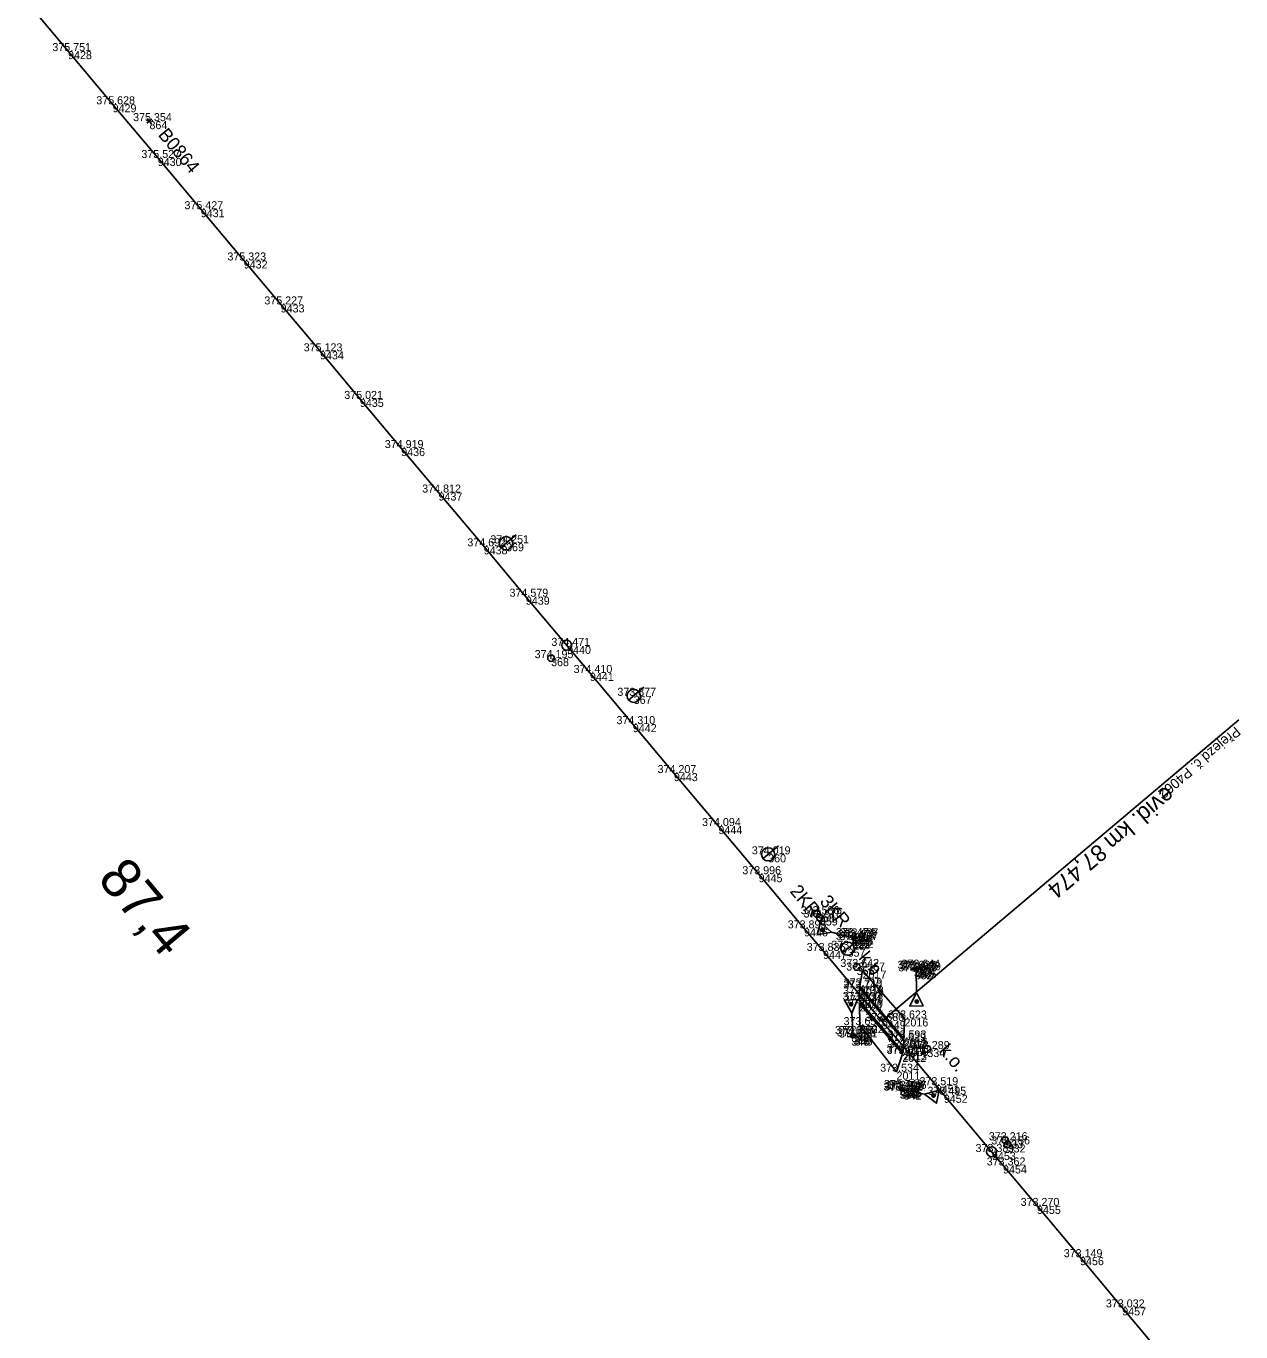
# Model space of a CAD drawing. Extents: x -599511 to -595511, y -1067427 to -1062061.
# Drawn here: x -596648.2 to -596466.1, y -1065669.8 to -1065474 of the extents above; entities that cross this region are included whole.
import ezdxf

# ---------------------------------------------------------------- set-up
doc = ezdxf.new("R2010")
doc.units = 0
for name, color, linetype in [('Vrstva 1', 7, 'Continuous'), ('Vrstva 12', 7, 'Continuous'), ('Vrstva 27', 7, 'Continuous'), ('Vrstva 4', 7, 'Continuous'), ('Vrstva 43', 7, 'Continuous'), ('Vrstva 50', 7, 'Continuous'), ('Vrstva 60', 7, 'Continuous'), ('Vrstva 61', 7, 'Continuous'), ('Vrstva 7', 7, 'Continuous')]:
    doc.layers.add(name, color=color, linetype=linetype)

msp = doc.modelspace()

# ---------------------------------------------------------------- linework, layer by layer
at = {"layer": 'Vrstva 1'}
msp.add_lwpolyline([(-596648.21, -1065470.29), (-596641.92, -1065477.78), (-596635.24, -1065485.75), (-596628.47, -1065493.8), (-596622.02, -1065501.48), (-596615.58, -1065509.16), (-596610.04, -1065515.75), (-596604.14, -1065522.78), (-596598.16, -1065529.91), (-596591.97, -1065537.28), (-596586.37, -1065543.95), (-596579.6, -1065552.01), (-596573.28, -1065559.56), (-596567.09, -1065566.93), (-596563.67, -1065570.99), (-596557.24, -1065578.66), (-596551.08, -1065586), (-596544.41, -1065593.94), (-596538.37, -1065601.16), (-596531.57, -1065609.27), (-596528.72, -1065612.66), (-596523.26, -1065619.18), (-596519.9, -1065623.17), (-596516.48, -1065627.21), (-596511.81, -1065632.78), (-596510.61, -1065634.22), (-596503.4, -1065642.8), (-596501.73, -1065644.81), (-596496.64, -1065650.88), (-596490.18, -1065658.56), (-596483.86, -1065666.09), (-596477.7, -1065673.43)], dxfattribs=at)
at = {"layer": 'Vrstva 12'}
for p, q in [((-596524.48, -1065625.11), (-596524.48, -1065625.11)), ((-596524.48, -1065625.65), (-596524.48, -1065625.65)), ((-596517.21, -1065633.58), (-596517.22, -1065633.59)), ((-596517.14, -1065633.2), (-596517.14, -1065633.2)), ((-596516.63, -1065633.73), (-596516.63, -1065633.73)), ((-596516.55, -1065633.33), (-596516.55, -1065633.33))]:
    msp.add_line(p, q, dxfattribs=at)
for points in [[(-596524.34, -1065610.43), (-596524.36, -1065610.97), (-596523.83, -1065611.03), (-596523.78, -1065610.48)], [(-596515.1, -1065615.33), (-596514.51, -1065615.16), (-596514.39, -1065615.56), (-596514.99, -1065615.71)], [(-596523.93, -1065625.1), (-596523.97, -1065625.63), (-596524.48, -1065625.65), (-596524.48, -1065625.11)], [(-596517.22, -1065633.59), (-596517.14, -1065633.2), (-596516.55, -1065633.33), (-596516.63, -1065633.73)], [(-596517.21, -1065633.58), (-596517.14, -1065633.2), (-596516.55, -1065633.33), (-596516.63, -1065633.73)]]:
    msp.add_lwpolyline(points, close=True, dxfattribs=at)
msp.add_lwpolyline([(-596523.97, -1065625.63), (-596524.48, -1065625.65), (-596524.48, -1065625.11), (-596523.93, -1065625.1)], dxfattribs=at)
at = {"layer": 'Vrstva 27'}
for p, q in [((-596529.65, -1065607.11), (-596529.59, -1065607.19)), ((-596529.23, -1065607.62), (-596529.17, -1065607.69)), ((-596523.71, -1065615.02), (-596523.64, -1065615.09)), ((-596513.12, -1065627.32), (-596513.05, -1065627.4))]:
    msp.add_line(p, q, dxfattribs=at)
for centre in [(-596529.62, -1065607.15), (-596529.2, -1065607.65), (-596523.67, -1065615.06), (-596513.08, -1065627.36)]:
    msp.add_circle(centre, 0.5, dxfattribs=at)
at = {"layer": 'Vrstva 4'}
for p, q in [((-596519.9, -1065623.17), (-596466.39, -1065578.04)), ((-596528.63, -1065609.71), (-596528.87, -1065609.29)), ((-596524.27, -1065611.48), (-596523.86, -1065609.98)), ((-596513.99, -1065615.41), (-596515.55, -1065615.43)), ((-596514.51, -1065620.09), (-596514.86, -1065620.43)), ((-596524.69, -1065620.82), (-596524.36, -1065620.46)), ((-596524.96, -1065625.52), (-596523.41, -1065625.42)), ((-596516.75, -1065632.68), (-596517.05, -1065634.2)), ((-596512.28, -1065634.14), (-596512.01, -1065634.55))]:
    msp.add_line(p, q, dxfattribs=at)
for points in [[(-596524.07, -1065610.73), (-596527.43, -1065609.83), (-596529.62, -1065610.26), (-596529.11, -1065608.33), (-596527.43, -1065609.83)], [(-596514.77, -1065615.42), (-596514.73, -1065618.9), (-596513.72, -1065620.89), (-596515.72, -1065620.92), (-596514.73, -1065618.9)], [(-596524.19, -1065625.47), (-596524.41, -1065622), (-596525.52, -1065620.06), (-596523.53, -1065619.93), (-596524.41, -1065622)], [(-596516.9, -1065633.44), (-596513.49, -1065634.11), (-596511.33, -1065633.53), (-596511.71, -1065635.49), (-596513.49, -1065634.11)]]:
    msp.add_lwpolyline(points, dxfattribs=at)
for points in [[(-596522.79, -1065615.6), (-596523.18, -1065617.97), (-596516.59, -1065625.78), (-596516.51, -1065622.78)], [(-596523.22, -1065618.28), (-596523.34, -1065620.02), (-596516.72, -1065627.85), (-596516.63, -1065626.1)], [(-596523.23, -1065620.52), (-596523.19, -1065623.78), (-596517.7, -1065630.76), (-596516.83, -1065628.1)]]:
    msp.add_lwpolyline(points, close=True, dxfattribs=at)
for centre in [(-596528.75, -1065609.5), (-596524.52, -1065620.64), (-596514.68, -1065620.26), (-596512.15, -1065634.35)]:
    msp.add_circle(centre, 0.248, dxfattribs=at)
at = {"layer": 'Vrstva 43'}
for p, q in [((-596574.72, -1065550.27), (-596577.02, -1065552.19)), ((-596555.58, -1065573.13), (-596557.87, -1065575.06)), ((-596535.41, -1065596.89), (-596537.71, -1065598.82)), ((-596523.51, -1065611.04), (-596525.81, -1065612.96))]:
    msp.add_line(p, q, dxfattribs=at)
for centre in [(-596576.25, -1065551.55), (-596557.11, -1065574.42), (-596536.95, -1065598.18), (-596525.04, -1065612.32)]:
    msp.add_circle(centre, 0.996, dxfattribs=at)
at = {"layer": 'Vrstva 50'}
msp.add_line((-596501.07, -1065641.62), (-596501.01, -1065641.7), dxfattribs=at)
msp.add_circle((-596501.04, -1065641.66), 0.5, dxfattribs=at)
at = {"layer": 'Vrstva 60'}
for p, q in [((-596641.92, -1065477.78), (-596641.92, -1065477.78)), ((-596635.24, -1065485.75), (-596635.24, -1065485.75)), ((-596629.72, -1065488.28), (-596629.72, -1065488.28)), ((-596628.47, -1065493.8), (-596628.47, -1065493.8)), ((-596622.02, -1065501.48), (-596622.02, -1065501.48)), ((-596615.58, -1065509.16), (-596615.58, -1065509.16)), ((-596610.04, -1065515.75), (-596610.04, -1065515.75)), ((-596604.14, -1065522.78), (-596604.14, -1065522.78)), ((-596598.16, -1065529.91), (-596598.16, -1065529.91)), ((-596591.97, -1065537.28), (-596591.97, -1065537.28)), ((-596586.37, -1065543.95), (-596586.37, -1065543.95)), ((-596576.25, -1065551.55), (-596576.25, -1065551.55)), ((-596579.6, -1065552.01), (-596579.6, -1065552.01)), ((-596573.28, -1065559.56), (-596573.28, -1065559.56)), ((-596567.09, -1065566.93), (-596567.09, -1065566.93)), ((-596569.5, -1065568.77), (-596569.5, -1065568.77)), ((-596563.67, -1065570.99), (-596563.67, -1065570.99)), ((-596557.11, -1065574.42), (-596557.11, -1065574.42)), ((-596557.24, -1065578.66), (-596557.24, -1065578.66)), ((-596551.08, -1065586), (-596551.08, -1065586)), ((-596544.41, -1065593.94), (-596544.41, -1065593.94)), ((-596536.95, -1065598.18), (-596536.95, -1065598.18)), ((-596538.37, -1065601.16), (-596538.37, -1065601.16)), ((-596529.62, -1065607.15), (-596529.62, -1065607.15)), ((-596529.2, -1065607.65), (-596529.2, -1065607.65)), ((-596531.57, -1065609.27), (-596531.57, -1065609.27)), ((-596524.34, -1065610.43), (-596524.34, -1065610.43)), ((-596523.78, -1065610.48), (-596523.78, -1065610.48)), ((-596525.04, -1065612.32), (-596525.04, -1065612.32)), ((-596524.36, -1065610.97), (-596524.36, -1065610.97)), ((-596524.07, -1065610.73), (-596524.07, -1065610.73)), ((-596523.83, -1065611.03), (-596523.83, -1065611.03)), ((-596528.72, -1065612.66), (-596528.72, -1065612.66)), ((-596523.67, -1065615.06), (-596523.67, -1065615.06)), ((-596522.79, -1065615.6), (-596522.79, -1065615.6)), ((-596515.1, -1065615.33), (-596515.1, -1065615.33)), ((-596514.99, -1065615.71), (-596514.99, -1065615.71)), ((-596514.77, -1065615.42), (-596514.77, -1065615.42)), ((-596514.51, -1065615.16), (-596514.51, -1065615.16)), ((-596514.39, -1065615.56), (-596514.39, -1065615.56)), ((-596523.22, -1065618.28), (-596523.22, -1065618.28)), ((-596523.18, -1065617.97), (-596523.18, -1065617.97)), ((-596523.34, -1065620.02), (-596523.34, -1065620.02)), ((-596523.26, -1065619.18), (-596523.26, -1065619.18)), ((-596523.23, -1065620.52), (-596523.23, -1065620.52)), ((-596523.19, -1065623.78), (-596523.19, -1065623.78)), ((-596519.9, -1065623.17), (-596519.9, -1065623.17)), ((-596516.51, -1065622.78), (-596516.51, -1065622.78)), ((-596524.48, -1065625.11), (-596524.48, -1065625.11)), ((-596524.48, -1065625.11), (-596524.48, -1065625.11)), ((-596524.48, -1065625.65), (-596524.48, -1065625.65)), ((-596524.48, -1065625.65), (-596524.48, -1065625.65)), ((-596524.19, -1065625.47), (-596524.19, -1065625.47)), ((-596523.97, -1065625.63), (-596523.97, -1065625.63)), ((-596523.93, -1065625.1), (-596523.93, -1065625.1)), ((-596516.63, -1065626.1), (-596516.63, -1065626.1)), ((-596516.59, -1065625.78), (-596516.59, -1065625.78)), ((-596516.83, -1065628.1), (-596516.83, -1065628.1)), ((-596516.72, -1065627.85), (-596516.72, -1065627.85)), ((-596516.48, -1065627.21), (-596516.48, -1065627.21)), ((-596513.08, -1065627.36), (-596513.08, -1065627.36)), ((-596517.7, -1065630.76), (-596517.7, -1065630.76)), ((-596517.22, -1065633.59), (-596517.22, -1065633.59)), ((-596517.21, -1065633.58), (-596517.21, -1065633.58)), ((-596517.14, -1065633.2), (-596517.14, -1065633.2)), ((-596517.14, -1065633.2), (-596517.14, -1065633.2)), ((-596516.9, -1065633.44), (-596516.9, -1065633.44)), ((-596516.63, -1065633.73), (-596516.63, -1065633.73)), ((-596516.63, -1065633.73), (-596516.63, -1065633.73)), ((-596516.55, -1065633.33), (-596516.55, -1065633.33)), ((-596516.55, -1065633.33), (-596516.55, -1065633.33)), ((-596511.81, -1065632.78), (-596511.81, -1065632.78)), ((-596510.61, -1065634.22), (-596510.61, -1065634.22)), ((-596501.41, -1065641.03), (-596501.41, -1065641.03)), ((-596501.04, -1065641.66), (-596501.04, -1065641.66)), ((-596503.4, -1065642.8), (-596503.4, -1065642.8)), ((-596501.73, -1065644.81), (-596501.73, -1065644.81)), ((-596496.64, -1065650.88), (-596496.64, -1065650.88)), ((-596490.18, -1065658.56), (-596490.18, -1065658.56)), ((-596483.86, -1065666.09), (-596483.86, -1065666.09))]:
    msp.add_line(p, q, dxfattribs=at)
at = {"layer": 'Vrstva 7'}
for p, q in [((-596629.34, -1065487.96), (-596630.1, -1065488.6)), ((-596630.04, -1065487.9), (-596629.4, -1065488.66)), ((-596569.54, -1065568.73), (-596569.47, -1065568.81)), ((-596501.44, -1065640.99), (-596501.38, -1065641.07))]:
    msp.add_line(p, q, dxfattribs=at)
for centre, radius in [((-596567.16, -1065566.84), 0.75), ((-596569.5, -1065568.77), 0.5), ((-596501.41, -1065641.03), 0.5), ((-596503.45, -1065642.75), 0.75)]:
    msp.add_circle(centre, radius, dxfattribs=at)

# ---------------------------------------------------------------- texts
at = {"layer": 'Vrstva 27'}
for s, rotation, p in [('2KR', 309.9948, (-596533.79, -1065603.76)), ('3KR', 310.0311, (-596529.32, -1065605.31)), ('k.o.', 309.9366, (-596523.47, -1065613.76)), ('k.o.', 309.9791, (-596511.42, -1065627.66))]:
    msp.add_text(s, height=2, rotation=rotation, dxfattribs=at).set_placement(p)
at = {"layer": 'Vrstva 4'}
for s, height, p in [('Přejezd č. P4062', 1.5, (-596466.91, -1065578.94)), ('evid. km 87,474', 2.5, (-596477.27, -1065587.84))]:
    msp.add_text(s, height=height, rotation=220.1449, dxfattribs=at).set_placement(p)
at = {"layer": 'Vrstva 60'}
for s, p in [('9428', (-596641.92, -1065478.98)), ('9429', (-596635.24, -1065486.95)), ('864', (-596629.72, -1065489.48)), ('9430', (-596628.47, -1065495)), ('9431', (-596622.02, -1065502.68)), ('9432', (-596615.58, -1065510.36)), ('9433', (-596610.04, -1065516.95)), ('9434', (-596604.14, -1065523.98)), ('9435', (-596598.16, -1065531.11)), ('9436', (-596591.97, -1065538.48)), ('9437', (-596586.37, -1065545.15)), ('369', (-596576.25, -1065552.75)), ('9438', (-596579.6, -1065553.21)), ('9439', (-596573.28, -1065560.76)), ('9440', (-596567.09, -1065568.13)), ('368', (-596569.5, -1065569.97)), ('9441', (-596563.67, -1065572.19)), ('367', (-596557.11, -1065575.62)), ('9442', (-596557.24, -1065579.86)), ('9443', (-596551.08, -1065587.2)), ('9444', (-596544.41, -1065595.14)), ('360', (-596536.95, -1065599.38)), ('9445', (-596538.37, -1065602.36)), ('358', (-596529.62, -1065608.35)), ('359', (-596529.2, -1065608.85)), ('9446', (-596531.57, -1065610.47)), ('354', (-596524.34, -1065611.63)), ('351', (-596523.78, -1065611.68)), ('357', (-596525.04, -1065613.52)), ('353', (-596524.36, -1065612.17)), ('355', (-596524.07, -1065611.93)), ('352', (-596523.83, -1065612.23)), ('9447', (-596528.72, -1065613.85)), ('356', (-596523.67, -1065616.26)), ('2017', (-596522.79, -1065616.8)), ('363', (-596515.1, -1065616.53)), ('362', (-596514.99, -1065616.91)), ('366', (-596514.77, -1065616.62)), ('364', (-596514.51, -1065616.36)), ('365', (-596514.39, -1065616.77)), ('2019', (-596523.22, -1065619.48)), ('2018', (-596523.18, -1065619.17)), ('2020', (-596523.34, -1065621.22)), ('9448', (-596523.26, -1065620.38)), ('2021', (-596523.23, -1065621.72)), ('2022', (-596523.19, -1065624.98)), ('9449', (-596519.9, -1065624.37)), ('2016', (-596516.51, -1065623.98)), ('348', (-596524.48, -1065626.31)), ('349', (-596524.48, -1065626.31)), ('346', (-596524.48, -1065626.85)), ('347', (-596524.48, -1065626.85)), ('350', (-596524.19, -1065626.67)), ('345', (-596523.97, -1065626.83)), ('344', (-596523.93, -1065626.3)), ('2014', (-596516.63, -1065627.3)), ('2015', (-596516.59, -1065626.98)), ('2012', (-596516.83, -1065629.3)), ('2013', (-596516.72, -1065629.05)), ('9450', (-596516.48, -1065628.41)), ('334', (-596513.08, -1065628.56)), ('2011', (-596517.7, -1065631.96)), ('340', (-596517.22, -1065634.79)), ('339', (-596517.21, -1065634.78)), ('337', (-596517.14, -1065634.4)), ('338', (-596517.14, -1065634.4)), ('343', (-596516.9, -1065634.64)), ('341', (-596516.63, -1065634.93)), ('342', (-596516.63, -1065634.93)), ('336', (-596516.55, -1065634.53)), ('335', (-596516.55, -1065634.53)), ('9451', (-596511.81, -1065633.98)), ('9452', (-596510.61, -1065635.42)), ('333', (-596501.41, -1065642.23)), ('332', (-596501.04, -1065642.86)), ('9453', (-596503.4, -1065644)), ('9454', (-596501.73, -1065646.01)), ('9455', (-596496.64, -1065652.08)), ('9456', (-596490.18, -1065659.76)), ('9457', (-596483.86, -1065667.29))]:
    msp.add_text(s, height=1.2, dxfattribs=at).set_placement(p)
at = {"layer": 'Vrstva 61'}
for s, p in [('375.751', (-596644.28, -1065477.78)), ('375.628', (-596637.69, -1065485.75)), ('375.354', (-596632.17, -1065488.28)), ('375.527', (-596630.93, -1065493.8)), ('375.427', (-596624.47, -1065501.48)), ('375.323', (-596618.03, -1065509.16)), ('375.227', (-596612.49, -1065515.75)), ('375.123', (-596606.59, -1065522.78)), ('375.021', (-596600.51, -1065529.91)), ('374.919', (-596594.43, -1065537.28)), ('374.812', (-596588.82, -1065543.95)), ('374.692', (-596582.05, -1065552.01)), ('374.251', (-596578.61, -1065551.55)), ('374.579', (-596575.73, -1065559.56)), ('374.195', (-596571.96, -1065568.77)), ('374.471', (-596569.45, -1065566.93)), ('374.410', (-596566.12, -1065570.99)), ('373.877', (-596559.56, -1065574.42)), ('374.310', (-596559.69, -1065578.66)), ('374.207', (-596553.53, -1065586)), ('374.094', (-596546.86, -1065593.94)), ('374.019', (-596539.4, -1065598.18)), ('373.996', (-596540.82, -1065601.16)), ('373.586', (-596532.07, -1065607.15)), ('373.578', (-596531.65, -1065607.65)), ('373.895', (-596534.02, -1065609.27)), ('373.468', (-596526.81, -1065610.97)), ('373.474', (-596526.79, -1065610.43)), ('373.472', (-596526.52, -1065610.73)), ('373.467', (-596526.28, -1065611.03)), ('373.487', (-596526.23, -1065610.48)), ('373.836', (-596531.17, -1065612.66)), ('373.222', (-596527.49, -1065612.32)), ('373.642', (-596526.12, -1065615.06)), ('373.567', (-596525.24, -1065615.6)), ('373.638', (-596517.56, -1065615.33)), ('373.646', (-596517.44, -1065615.71)), ('373.645', (-596517.22, -1065615.42)), ('373.644', (-596516.96, -1065615.16)), ('373.639', (-596516.85, -1065615.56)), ('373.734', (-596525.71, -1065619.18)), ('373.740', (-596525.68, -1065618.28)), ('373.719', (-596525.63, -1065617.97)), ('373.732', (-596525.79, -1065620.02)), ('373.671', (-596525.59, -1065620.52)), ('373.680', (-596522.35, -1065623.17)), ('373.623', (-596518.96, -1065622.78)), ('373.128', (-596526.93, -1065625.11)), ('373.627', (-596526.93, -1065625.11)), ('373.656', (-596526.64, -1065625.47)), ('373.650', (-596526.38, -1065625.1)), ('373.652', (-596525.64, -1065623.78)), ('373.624', (-596526.93, -1065625.65)), ('373.124', (-596526.93, -1065625.65)), ('373.611', (-596526.33, -1065625.63)), ('373.629', (-596519.08, -1065626.1)), ('373.593', (-596519.04, -1065625.78)), ('373.617', (-596518.93, -1065627.21)), ('373.289', (-596515.54, -1065627.36)), ('373.611', (-596519.18, -1065628.1)), ('373.618', (-596519.18, -1065627.85)), ('373.534', (-596520.15, -1065630.76)), ('373.443', (-596519.59, -1065633.2)), ('373.743', (-596519.59, -1065633.2)), ('373.746', (-596519, -1065633.33)), ('373.447', (-596519, -1065633.33)), ('373.519', (-596514.26, -1065632.78)), ('373.752', (-596519.66, -1065633.58)), ('373.451', (-596519.58, -1065633.59)), ('373.743', (-596519.35, -1065633.44)), ('373.449', (-596519.09, -1065633.73)), ('373.749', (-596519.08, -1065633.73)), ('373.495', (-596513.06, -1065634.22)), ('373.216', (-596503.86, -1065641.03)), ('373.389', (-596505.85, -1065642.8)), ('373.156', (-596503.49, -1065641.66)), ('373.362', (-596504.18, -1065644.81)), ('373.270', (-596499.09, -1065650.88)), ('373.149', (-596492.63, -1065658.56)), ('373.032', (-596486.31, -1065666.09))]:
    msp.add_text(s, height=1.2, dxfattribs=at).set_placement(p)
at = {"layer": 'Vrstva 7'}
for s, height, rotation, p in [('B0864', 2, 310.0323, (-596628.53, -1065490.37)), ('87,4', 6, 310.0252, (-596637.66, -1065601.95))]:
    msp.add_text(s, height=height, rotation=rotation, dxfattribs=at).set_placement(p)

doc.saveas('drawing.dxf')
